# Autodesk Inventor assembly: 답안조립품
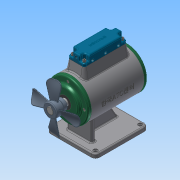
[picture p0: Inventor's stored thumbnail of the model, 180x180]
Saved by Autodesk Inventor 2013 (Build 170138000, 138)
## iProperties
Created: 2019-07
Part Number: 답안조립품
Document SubType Name: Assembly
Designer: Administrator
Mass: 3420.46 g
Surface Area: 2825.52 cm^2
Volume: 1021.29 cm^3
Density: 3.34915 g/cm^3
Author: Administrator
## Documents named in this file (19)
- C:\Users\Administrator\Desktop\390704V1071\답안조립품.iam
- C:\Users\Administrator\Desktop\390704V1071\본체.ipt
- C:\Users\Administrator\Desktop\390704V1071\가변스프링.ipt
- C:\Users\Administrator\Desktop\390704V1071\가변스프링2.ipt
- C:\Users\Administrator\Desktop\390704V1071\가변스프링3.ipt
- C:\Users\Administrator\Desktop\390704V1071\뒤커버.ipt
- C:\Users\Administrator\Desktop\390704V1071\멈춤나사 M4 x 5.ipt
- C:\Users\Administrator\Desktop\390704V1071\베어링 6203.ipt
- C:\Users\Administrator\Desktop\390704V1071\볼트 M4 x 12.ipt
- C:\Users\Administrator\Desktop\390704V1071\볼트 M4 x 16.ipt
- C:\Users\Administrator\Desktop\390704V1071\부시.ipt
- C:\Users\Administrator\Desktop\390704V1071\슬라이드.ipt
- C:\Users\Administrator\Desktop\390704V1071\앞커버.ipt
- C:\Users\Administrator\Desktop\390704V1071\오일실 17 30 8.ipt
- C:\Users\Administrator\Desktop\390704V1071\축.ipt
- C:\Users\Administrator\Desktop\390704V1071\키 5 x 5 x 18.ipt
- C:\Users\Administrator\Desktop\390704V1071\팬날개.ipt
- 팬날개.ipt
- C:\Users\Administrator\Desktop\390704V1071\헤더커버.ipt
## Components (4 placed, 4 different names)
1. 가변스프링:1
2. 가변스프링2:1
3. 가변스프링3:1
4. 헤더커버:1
